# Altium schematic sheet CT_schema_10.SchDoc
size 382 x 278 mm
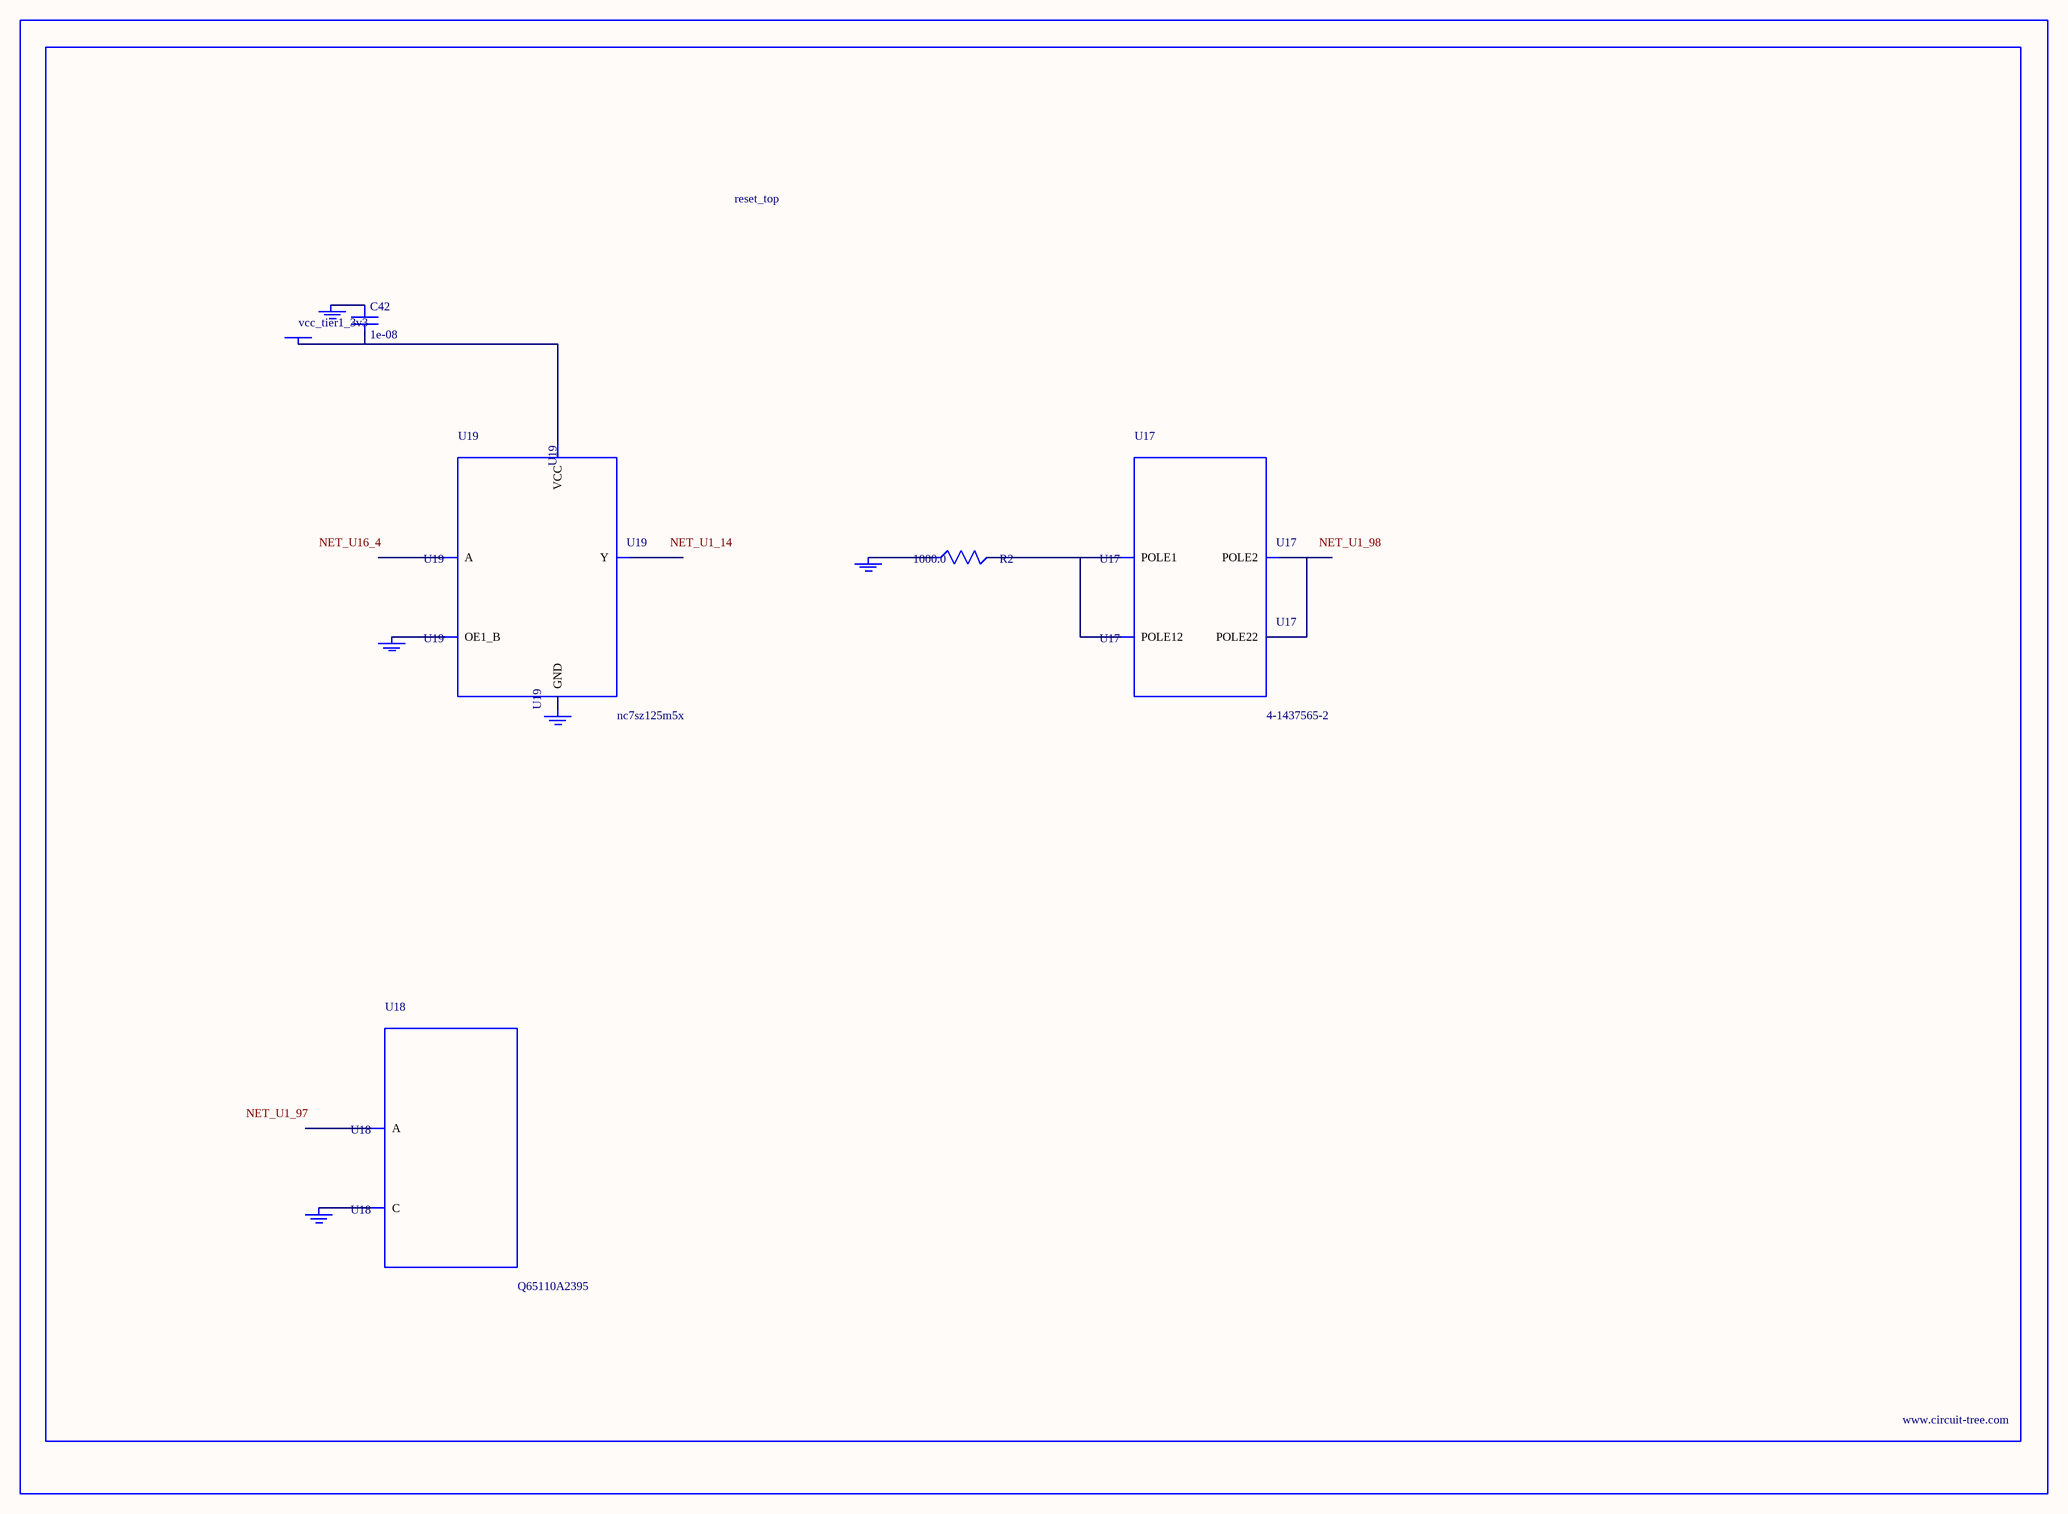
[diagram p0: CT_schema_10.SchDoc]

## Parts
BORDER9  (no value)
C42  1e-08  [C0402]
GND_INSTANCE_9_0  (no value)
GND_INSTANCE_9_1  (no value)
GND_INSTANCE_9_2  (no value)
GND_INSTANCE_9_3  (no value)
GND_INSTANCE_9_4  (no value)
POWER_INSTANCE_9_0  vcc_tier1_3v3
R2  1000.0  [R0603]
U17  4-1437565-2  [SW_4-1437565-2]
U18  Q65110A2395  [LGM67K-G1J2-24-Z]
U19  nc7sz125m5x  [NC7SZ125M5X]

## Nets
NetC42_1: C42.1 GND_INSTANCE_9_2.0(GND)
NetC42_2: C42.2 POWER_INSTANCE_9_0.0(PWR) U19.5(VCC)
NetGND_INSTANCE_9_0_0: GND_INSTANCE_9_0.0(GND) R2.1
NetGND_INSTANCE_9_1_0: GND_INSTANCE_9_1.0(GND) U18.C
NetGND_INSTANCE_9_3_0: GND_INSTANCE_9_3.0(GND) U19.1(OE1_B)
NetGND_INSTANCE_9_4_0: GND_INSTANCE_9_4.0(GND) U19.3(GND)
NetR2_2: R2.2 U17.1(POLE1) U17.2(POLE12)
NetU17_3: U17.3(POLE2) U17.4(POLE22)

Not connected (* = marked no-connect by the designer): U18 A; U19 2(A) 4(Y)

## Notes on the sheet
- Labels drawn without touching a wire or pin: NET_U1_14, NET_U1_97, NET_U1_98, NET_U16_4

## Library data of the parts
BORDER9 = BORDER_PAGE9
C42 = C0402C103K3RAC
GND_INSTANCE_9_0-GND_INSTANCE_9_4 = GND
POWER_INSTANCE_9_0 = PWR
R2 = RC0603JR-071KL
